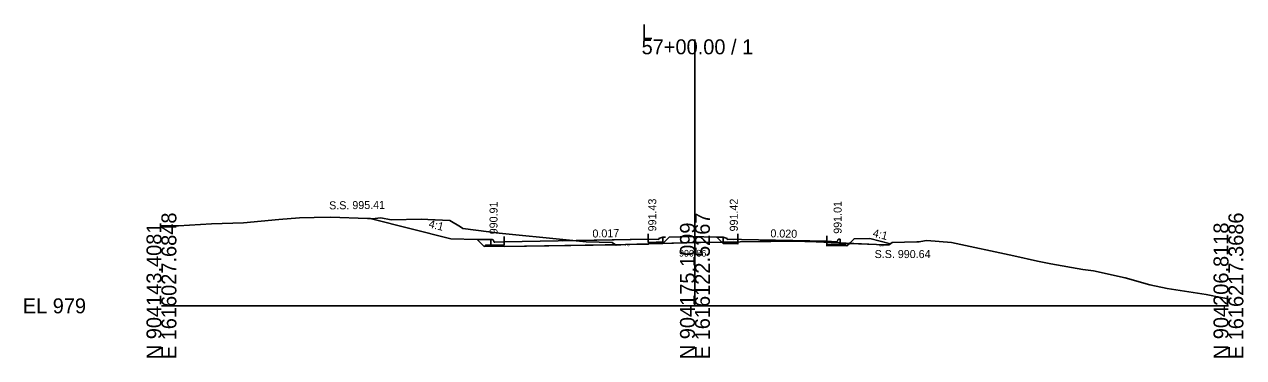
# Model space of a CAD drawing. Extents: x 1009 to 7438, y -1586 to 7964.
# Drawn here: x 5009.2 to 5237.7, y 4914 to 4976.4 of the extents above; entities that cross this region are included whole.
import ezdxf

# ---------------------------------------------------------------- set-up
doc = ezdxf.new("R2010")
doc.units = 0
for name, color, linetype in [('Exist Cross Section Cell', 7, 'Continuous'), ('Exist XS Center Line Elevation Label', 7, 'Continuous'), ('Exist XS Ground Line', 7, 'Continuous'), ('Prop XS Dump Level', 7, 'Continuous'), ('Prop XS Earthwork Shape', 7, 'Continuous'), ('Prop XS EOT Tick Mark', 7, 'Continuous'), ('Prop XS Finish Grade', 7, 'Continuous'), ('Prop XS Finish Grade CurbGutter', 7, 'Continuous'), ('Prop XS Finish Grade Earthwork', 7, 'Continuous'), ('Prop XS Finish Grade Pavement', 7, 'Continuous'), ('Prop XS Hydro Elevations', 7, 'Continuous'), ('Prop XS Pvmt Edge Slope', 7, 'Continuous'), ('Prop XS SE Text', 7, 'Continuous'), ('Prop XS Side Slope Text', 7, 'Continuous'), ('Prop XS SS Elevation Text', 7, 'Continuous'), ('Prop XS Subgrade CurbGutter', 7, 'Continuous'), ('Prop XS Subgrade Earthwork', 7, 'Continuous')]:
    doc.layers.add(name, color=color, linetype=linetype)

msp = doc.modelspace()

# ---------------------------------------------------------------- linework, layer by layer
at = {"layer": 'Exist Cross Section Cell'}
for p, q in [((5134.89, 4923.73), (5134.89, 4973.65)), ((5034.89, 4923.73), (5134.89, 4923.73)), ((5134.89, 4923.73), (5234.89, 4923.73))]:
    msp.add_line(p, q, dxfattribs=at)
at = {"layer": 'Exist XS Ground Line'}
for p, q in [((5034.89, 4938.69), (5036.15, 4938.7)), ((5036.15, 4938.7), (5038.07, 4938.72)), ((5038.07, 4938.72), (5044.27, 4939.09)), ((5044.27, 4939.09), (5050.29, 4939.29)), ((5050.29, 4939.29), (5056.87, 4939.88)), ((5056.87, 4939.88), (5060.79, 4940.2)), ((5060.79, 4940.2), (5063.52, 4940.31)), ((5063.52, 4940.31), (5066.58, 4940.37)), ((5066.58, 4940.37), (5073.52, 4940.07)), ((5073.52, 4940.07), (5074.05, 4940.07)), ((5074.05, 4940.07), (5074.38, 4940.05)), ((5074.38, 4940.05), (5076.01, 4940.21)), ((5076.01, 4940.21), (5077.95, 4939.87)), ((5077.95, 4939.87), (5083.62, 4939.94)), ((5083.62, 4939.94), (5084.81, 4939.91)), ((5084.81, 4939.91), (5088.93, 4939.72)), ((5088.93, 4939.72), (5090.94, 4938.53)), ((5090.94, 4938.53), (5091.37, 4938.23)), ((5091.37, 4938.23), (5093.8, 4937.93)), ((5093.8, 4937.93), (5098.2, 4937.37)), ((5098.2, 4937.37), (5110.73, 4936.09)), ((5110.73, 4936.09), (5114.47, 4935.75)), ((5114.47, 4935.75), (5119.35, 4935.61)), ((5119.35, 4935.61), (5120.11, 4935.11)), ((5120.11, 4935.11), (5121.87, 4935.22)), ((5121.87, 4935.22), (5134.89, 4935.59)), ((5134.89, 4935.59), (5135.95, 4935.62)), ((5135.95, 4935.62), (5147.09, 4935.79)), ((5147.09, 4935.79), (5149.1, 4935.81)), ((5149.1, 4935.81), (5152.44, 4935.86)), ((5152.44, 4935.86), (5155.49, 4935.79)), ((5155.49, 4935.79), (5157.64, 4935.73)), ((5157.64, 4935.73), (5168.89, 4935.2)), ((5168.89, 4935.2), (5169.48, 4935.18)), ((5169.48, 4935.18), (5171.26, 4935.15)), ((5171.26, 4935.15), (5171.87, 4935.62)), ((5171.87, 4935.62), (5176.48, 4935.72)), ((5176.48, 4935.72), (5176.91, 4935.73)), ((5176.91, 4935.73), (5177.9, 4935.91)), ((5177.9, 4935.91), (5178.33, 4935.95)), ((5178.33, 4935.95), (5182.98, 4935.62)), ((5182.98, 4935.62), (5194.68, 4933.11)), ((5194.68, 4933.11), (5199.07, 4932.12)), ((5199.07, 4932.12), (5199.71, 4931.98)), ((5199.71, 4931.98), (5201.62, 4931.63)), ((5201.62, 4931.63), (5207.61, 4930.54)), ((5207.61, 4930.54), (5209.61, 4930.28)), ((5209.61, 4930.28), (5215.51, 4928.99)), ((5215.51, 4928.99), (5220.15, 4927.68)), ((5220.15, 4927.68), (5223.41, 4926.99)), ((5223.41, 4926.99), (5230.7, 4925.84)), ((5230.7, 4925.84), (5231.32, 4925.76)), ((5231.32, 4925.76), (5233.16, 4925.37)), ((5233.16, 4925.37), (5234.89, 4925.04))]:
    msp.add_line(p, q, dxfattribs=at)
at = {"layer": 'Prop XS Dump Level'}
for p, q in [((5110.14, 4935.93), (5126.14, 4936.2)), ((5110.14, 4935.93), (5126.14, 4936.2)), ((5142.92, 4936.19), (5143.64, 4936.17)), ((5142.92, 4936.19), (5143.64, 4936.17)), ((5143.64, 4936.17), (5159.64, 4935.85)), ((5143.64, 4936.17), (5159.64, 4935.85))]:
    msp.add_line(p, q, dxfattribs=at)
at = {"layer": 'Prop XS Earthwork Shape'}
for points in [[(5074.01, 4940.07), (5074.05, 4940.07), (5074.38, 4940.05), (5076.01, 4940.21), (5077.95, 4939.87), (5083.62, 4939.94), (5084.81, 4939.91), (5088.93, 4939.72), (5090.94, 4938.53), (5091.37, 4938.23), (5093.8, 4937.93), (5098.2, 4937.37), (5110.73, 4936.09), (5114.47, 4935.75), (5119.35, 4935.61), (5120.01, 4935.18), (5099.14, 4934.82), (5099.14, 4934.91), (5095.39, 4934.85), (5095.64, 4935.1), (5096.64, 4935.12), (5099.14, 4935.16), (5099.14, 4935.74), (5097.39, 4935.64), (5097.27, 4935.67), (5097.18, 4935.76), (5097.11, 4936.01), (5097.02, 4936.1), (5096.89, 4936.13), (5096.64, 4936.13), (5094.06, 4936.18), (5089.14, 4936.29)], [(5139.91, 4935.68), (5139, 4936.59), (5138.95, 4936.59), (5134.17, 4936.69), (5130.08, 4936.61), (5128.89, 4935.42), (5134.89, 4935.59), (5135.95, 4935.62)], [(5169.48, 4935.18), (5171.26, 4935.15), (5171.55, 4935.37), (5167.64, 4936.35), (5164.73, 4936.29), (5163.88, 4935.44), (5168.89, 4935.2)], [(5095.64, 4935.1), (5095.39, 4934.85), (5094.06, 4936.18), (5096.64, 4936.13), (5096.64, 4935.12)], [(5097.11, 4936.01), (5097.02, 4936.1), (5096.89, 4936.13), (5096.64, 4936.13), (5096.64, 4935.12), (5099.14, 4935.16), (5099.14, 4935.74), (5097.39, 4935.64), (5097.27, 4935.67), (5097.18, 4935.76)], [(5120.11, 4935.11), (5121.87, 4935.21), (5120.01, 4935.18)], [(5121.87, 4935.21), (5126.14, 4935.34), (5126.14, 4935.28)], [(5126.14, 4935.34), (5126.14, 4935.37), (5128.89, 4935.42)], [(5140.18, 4935.41), (5139.91, 4935.68), (5140.17, 4935.68), (5140.17, 4935.66), (5140.42, 4935.66)], [(5142.92, 4935.61), (5141.42, 4935.64), (5140.42, 4935.66), (5140.17, 4935.66), (5140.17, 4935.68), (5142.92, 4935.72)], [(5142.92, 4935.61), (5141.42, 4935.64), (5140.42, 4935.66), (5140.18, 4935.41), (5142.92, 4935.36)], [(5159.64, 4935.64), (5159.64, 4935.27), (5162.14, 4935.22), (5162.14, 4935.52)], [(5163.14, 4935.2), (5163.39, 4934.95), (5159.64, 4935.02), (5159.64, 4935.27), (5162.14, 4935.22)], [(5163.39, 4934.95), (5163.88, 4935.44), (5162.14, 4935.52), (5162.14, 4935.22), (5163.14, 4935.2)]]:
    msp.add_lwpolyline(points, close=True, dxfattribs=at)
at = {"layer": 'Prop XS EOT Tick Mark'}
for p, q in [((5099.14, 4935.74), (5099.14, 4936.74)), ((5126.14, 4936.2), (5126.14, 4937.2)), ((5142.92, 4936.19), (5142.92, 4937.19)), ((5159.64, 4935.85), (5159.64, 4936.85))]:
    msp.add_line(p, q, dxfattribs=at)
at = {"layer": 'Prop XS Finish Grade'}
for p, q in [((5128.89, 4936.58), (5129.4, 4936.59)), ((5140.17, 4936.57), (5138.95, 4936.59)), ((5096.64, 4936.13), (5094.06, 4936.18))]:
    msp.add_line(p, q, dxfattribs=at)
at = {"layer": 'Prop XS Finish Grade CurbGutter'}
for p, q in [((5128.14, 4936.33), (5128.89, 4936.58)), ((5128.14, 4936.16), (5128.14, 4936.33)), ((5140.92, 4936.32), (5140.17, 4936.57)), ((5140.92, 4936.15), (5140.92, 4936.32)), ((5096.64, 4936.13), (5096.89, 4936.13)), ((5096.89, 4936.13), (5097.02, 4936.1)), ((5097.11, 4936.01), (5097.02, 4936.1)), ((5097.18, 4935.76), (5097.11, 4936.01)), ((5097.27, 4935.67), (5097.18, 4935.76)), ((5097.39, 4935.64), (5097.27, 4935.67)), ((5099.14, 4935.74), (5097.39, 4935.64)), ((5126.14, 4936.2), (5128.14, 4936.16)), ((5142.92, 4936.19), (5140.92, 4936.15)), ((5142.92, 4936.19), (5142.17, 4936.17)), ((5159.64, 4935.85), (5161.39, 4935.75)), ((5161.39, 4935.75), (5161.52, 4935.77)), ((5161.52, 4935.77), (5161.61, 4935.86)), ((5161.61, 4935.86), (5161.68, 4936.11)), ((5161.68, 4936.11), (5161.77, 4936.21)), ((5161.89, 4936.23), (5161.77, 4936.21)), ((5162.14, 4936.23), (5161.89, 4936.23))]:
    msp.add_line(p, q, dxfattribs=at)
at = {"layer": 'Prop XS Finish Grade Earthwork'}
for p, q in [((5089.14, 4936.29), (5074.01, 4940.07)), ((5130.08, 4936.61), (5134.17, 4936.69)), ((5134.17, 4936.69), (5138.95, 4936.59)), ((5164.73, 4936.29), (5167.64, 4936.35)), ((5167.64, 4936.35), (5171.55, 4935.37)), ((5094.06, 4936.18), (5089.14, 4936.29))]:
    msp.add_line(p, q, dxfattribs=at)
at = {"layer": 'Prop XS Finish Grade Pavement'}
for p, q in [((5099.14, 4935.74), (5126.14, 4936.2)), ((5142.92, 4936.19), (5143.64, 4936.17)), ((5143.64, 4936.17), (5159.64, 4935.85))]:
    msp.add_line(p, q, dxfattribs=at)
at = {"layer": 'Prop XS Pvmt Edge Slope'}
for p, q in [((5095.64, 4935.1), (5095.39, 4934.85)), ((5096.64, 4935.12), (5095.64, 4935.1)), ((5127.64, 4935.65), (5128.89, 4935.67)), ((5128.64, 4935.66), (5128.89, 4935.42)), ((5141.42, 4935.64), (5140.17, 4935.66)), ((5140.42, 4935.66), (5140.18, 4935.41)), ((5162.14, 4935.22), (5163.14, 4935.2)), ((5163.14, 4935.2), (5163.39, 4934.95))]:
    msp.add_line(p, q, dxfattribs=at)
at = {"layer": 'Prop XS Subgrade CurbGutter'}
for p, q in [((5128.89, 4935.68), (5128.89, 4936.58)), ((5140.17, 4935.66), (5140.17, 4936.57)), ((5096.64, 4935.12), (5096.64, 4936.13)), ((5099.14, 4935.16), (5096.64, 4935.12)), ((5099.14, 4935.74), (5099.14, 4935.16)), ((5126.14, 4936.2), (5126.14, 4935.62)), ((5126.14, 4935.62), (5127.64, 4935.65)), ((5142.92, 4935.61), (5141.42, 4935.64)), ((5142.92, 4936.19), (5142.92, 4935.61)), ((5159.64, 4935.85), (5159.64, 4935.27)), ((5159.64, 4935.27), (5162.14, 4935.22)), ((5162.14, 4935.22), (5162.14, 4936.23))]:
    msp.add_line(p, q, dxfattribs=at)
at = {"layer": 'Prop XS Subgrade Earthwork'}
for p, q in [((5128.89, 4935.42), (5130.08, 4936.61)), ((5140.18, 4935.41), (5139, 4936.59)), ((5095.39, 4934.85), (5094.06, 4936.18)), ((5099.14, 4934.91), (5095.39, 4934.85)), ((5121.87, 4935.21), (5099.14, 4934.82)), ((5099.14, 4934.82), (5099.14, 4934.91)), ((5121.87, 4935.21), (5126.14, 4935.28)), ((5121.87, 4935.21), (5121.87, 4935.22)), ((5121.87, 4935.21), (5121.87, 4935.22)), ((5126.14, 4935.37), (5128.89, 4935.42)), ((5126.14, 4935.28), (5126.14, 4935.37)), ((5142.92, 4935.36), (5140.18, 4935.41)), ((5142.92, 4935.27), (5142.92, 4935.72)), ((5142.92, 4935.27), (5142.92, 4935.36)), ((5159.64, 4934.94), (5159.64, 4935.64)), ((5159.64, 4934.94), (5159.64, 4935.02)), ((5159.64, 4935.02), (5163.39, 4934.95)), ((5163.39, 4934.95), (5164.73, 4936.29))]:
    msp.add_line(p, q, dxfattribs=at)

# ---------------------------------------------------------------- texts
at = {"layer": 'Exist Cross Section Cell'}
for s, p in [('L', (5124.89, 4973.65)), ('57+00.00 / 1', (5124.89, 4970.85)), ('EL 979', (5008.89, 4922.33))]:
    msp.add_text(s, height=2.8, dxfattribs=at).set_placement(p)
for s, p in [('E 1616027.6848', (5037.69, 4913.73)), ('E 1616122.5267', (5137.69, 4913.73)), ('E 1616217.3686', (5237.69, 4913.73)), ('N 904143.4081', (5034.89, 4913.73)), ('N 904175.1099', (5134.89, 4913.73)), ('N 904206.8118', (5234.89, 4913.73))]:
    msp.add_text(s, height=2.8, rotation=90, dxfattribs=at).set_placement(p)
at = {"layer": 'Exist XS Center Line Elevation Label'}
msp.add_text('990.86', height=1.25, dxfattribs=at).set_placement((5131.91, 4932.96))
at = {"layer": 'Prop XS Dump Level'}
for p in [(5121.87, 4934.92), (5121.87, 4934.92), (5121.87, 4934.92), (5169.48, 4934.88)]:
    msp.add_text('Eop', height=0.3, dxfattribs=at).set_placement(p)
at = {"layer": 'Prop XS Hydro Elevations'}
for s, p in [('990.91', (5097.89, 4937.13)), ('991.43', (5127.64, 4937.68)), ('991.42', (5142.92, 4937.67)), ('991.01', (5162.39, 4937.23))]:
    msp.add_text(s, height=1.5, rotation=90, dxfattribs=at).set_placement(p)
at = {"layer": 'Prop XS SE Text'}
for s, rotation, p in [('0.017', 0.9749, (5115.69, 4936.52)), ('0.020', 358.8542, (5149.02, 4936.57))]:
    msp.add_text(s, height=1.5, rotation=rotation, dxfattribs=at).set_placement(p)
at = {"layer": 'Prop XS Side Slope Text'}
for p in [(5084.88, 4938.44), (5168.1, 4936.72)]:
    msp.add_text('4:1', height=1.5, rotation=345.9638, dxfattribs=at).set_placement(p)
at = {"layer": 'Prop XS SS Elevation Text'}
msp.add_text('S.S. 995.41', height=1.5, rotation=0.5729, dxfattribs=at).set_placement((5066.33, 4941.8))
msp.add_text('S.S. 990.64', height=1.5, dxfattribs=at).set_placement((5168.57, 4932.68))

doc.saveas('drawing.dxf')
